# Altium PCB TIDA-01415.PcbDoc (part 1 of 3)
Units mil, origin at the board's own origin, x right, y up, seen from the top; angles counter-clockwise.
Board outline 3820.95 x 4648 mil, 4 copper layers (Top Layer, GND, PWR, Bottom Layer), stack 5.6 mil thick; 255 components, 113 nets, 599 pads, 415 vias.
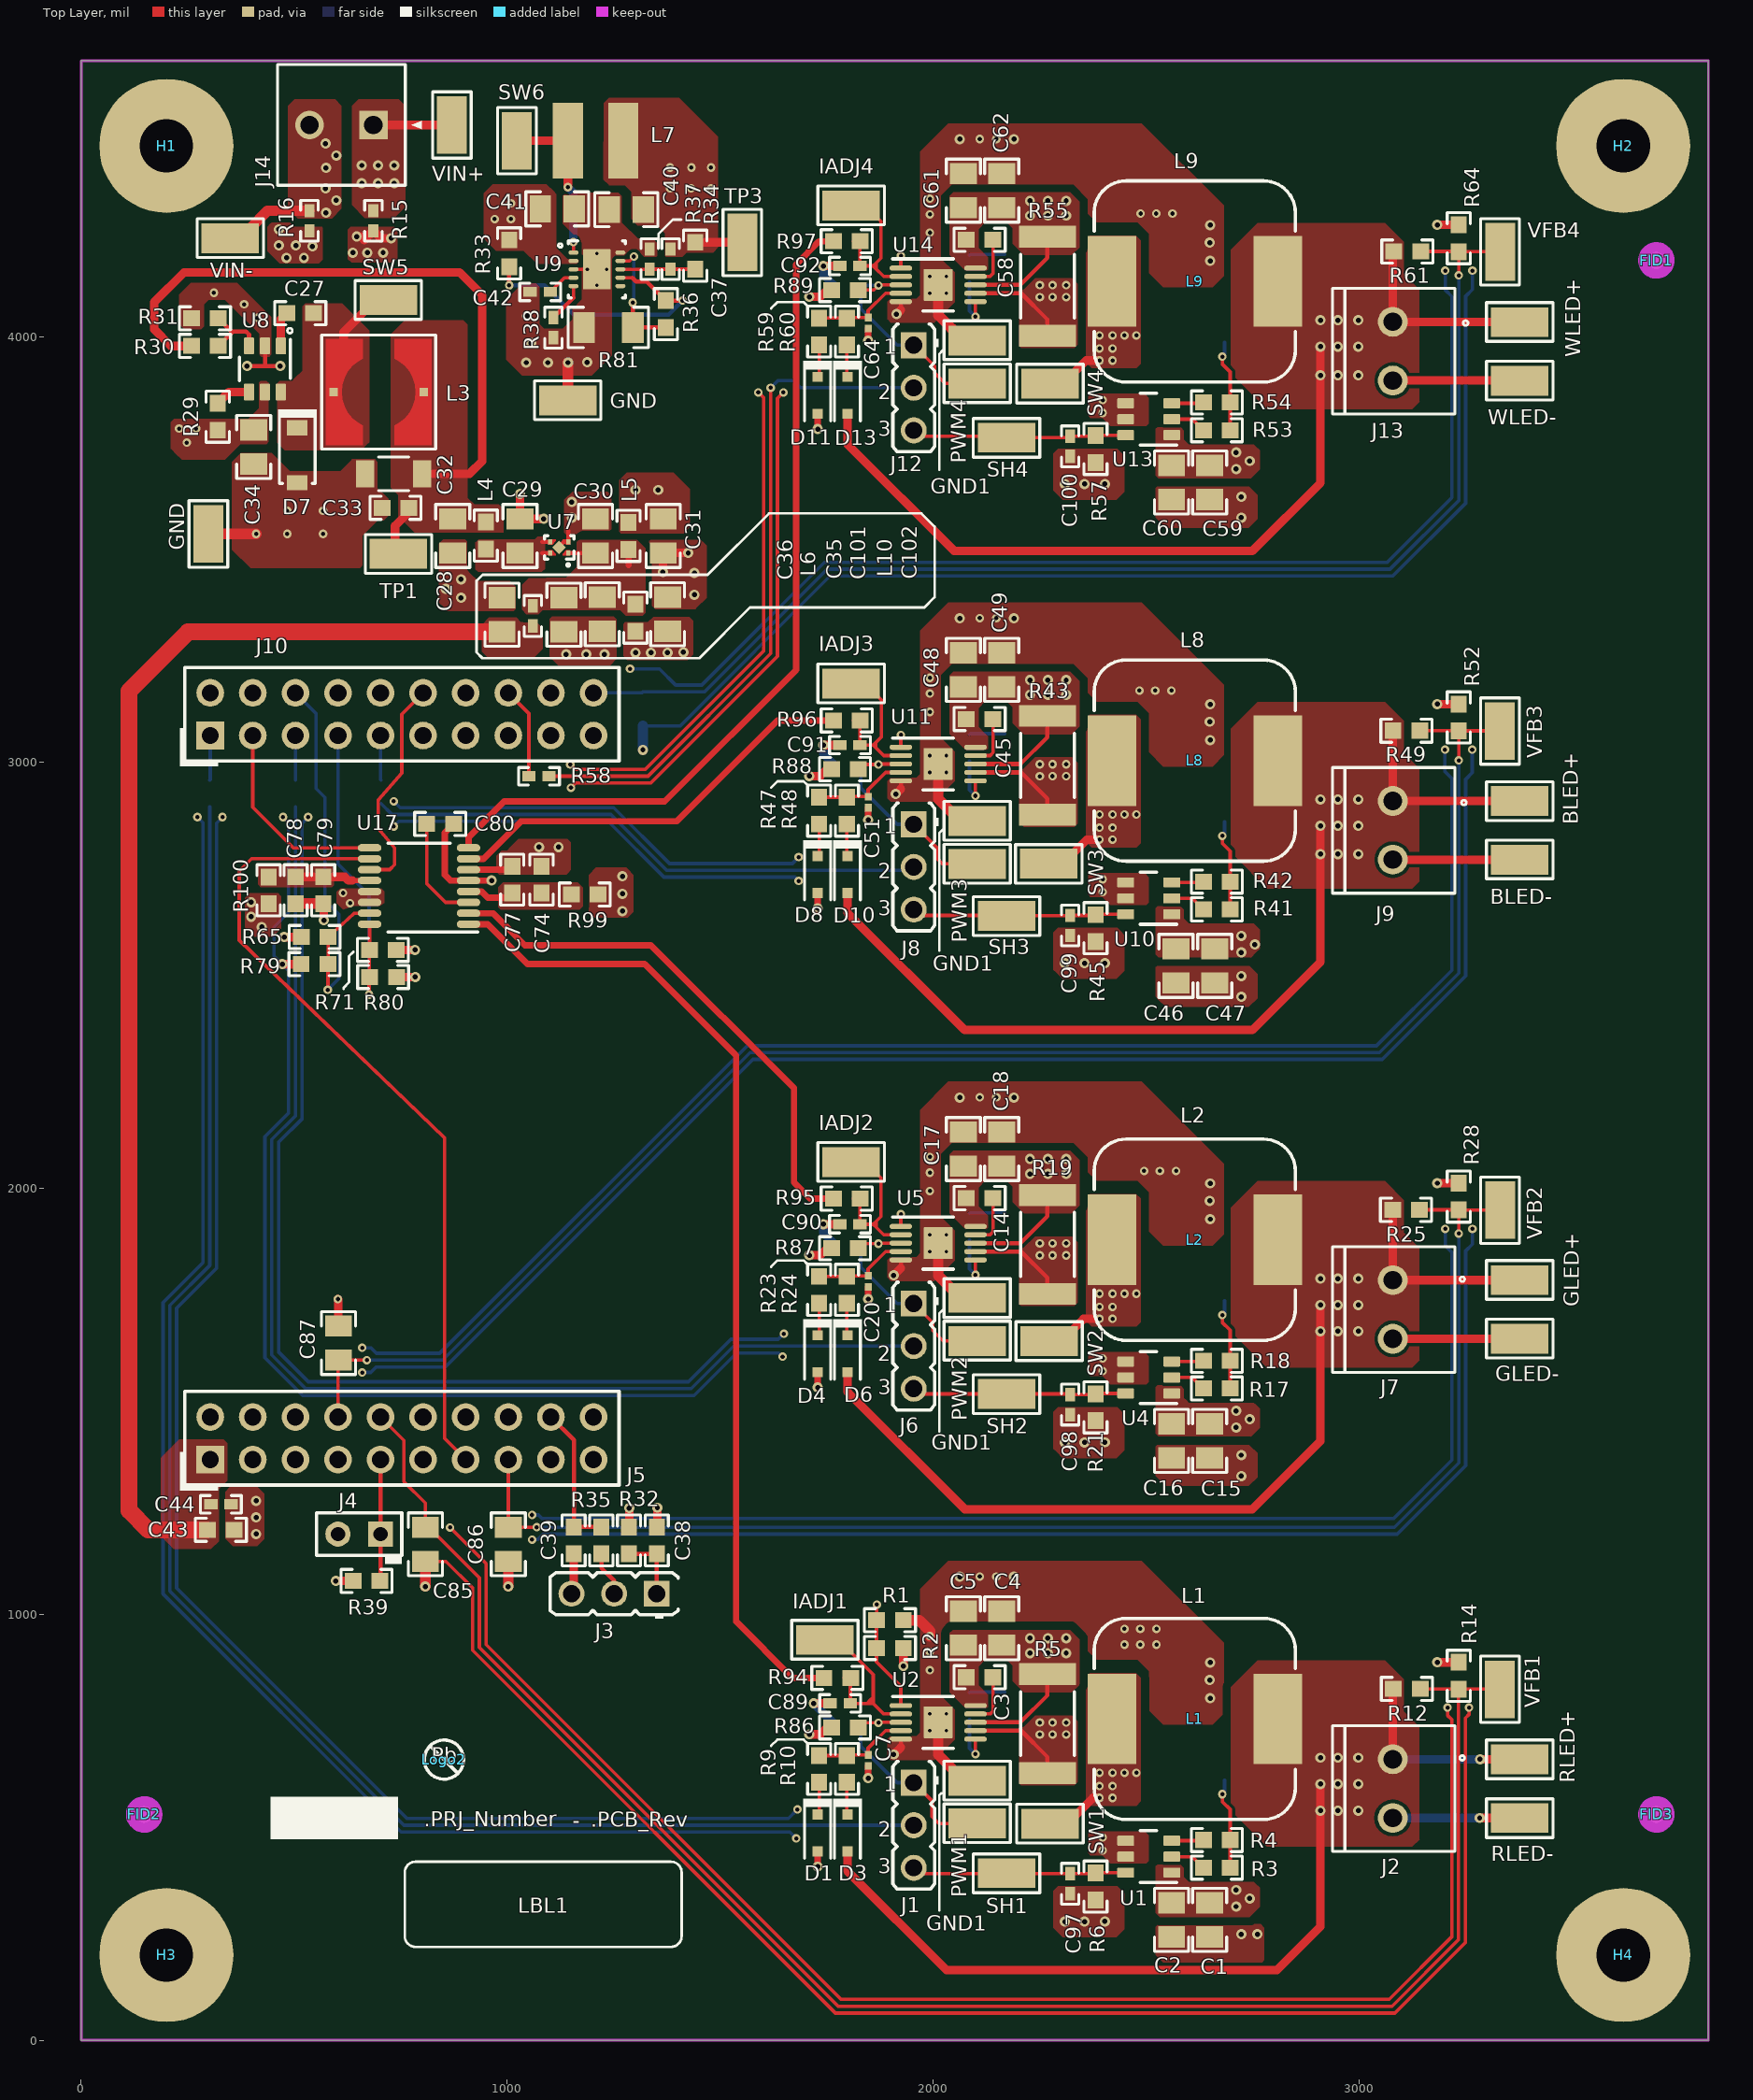
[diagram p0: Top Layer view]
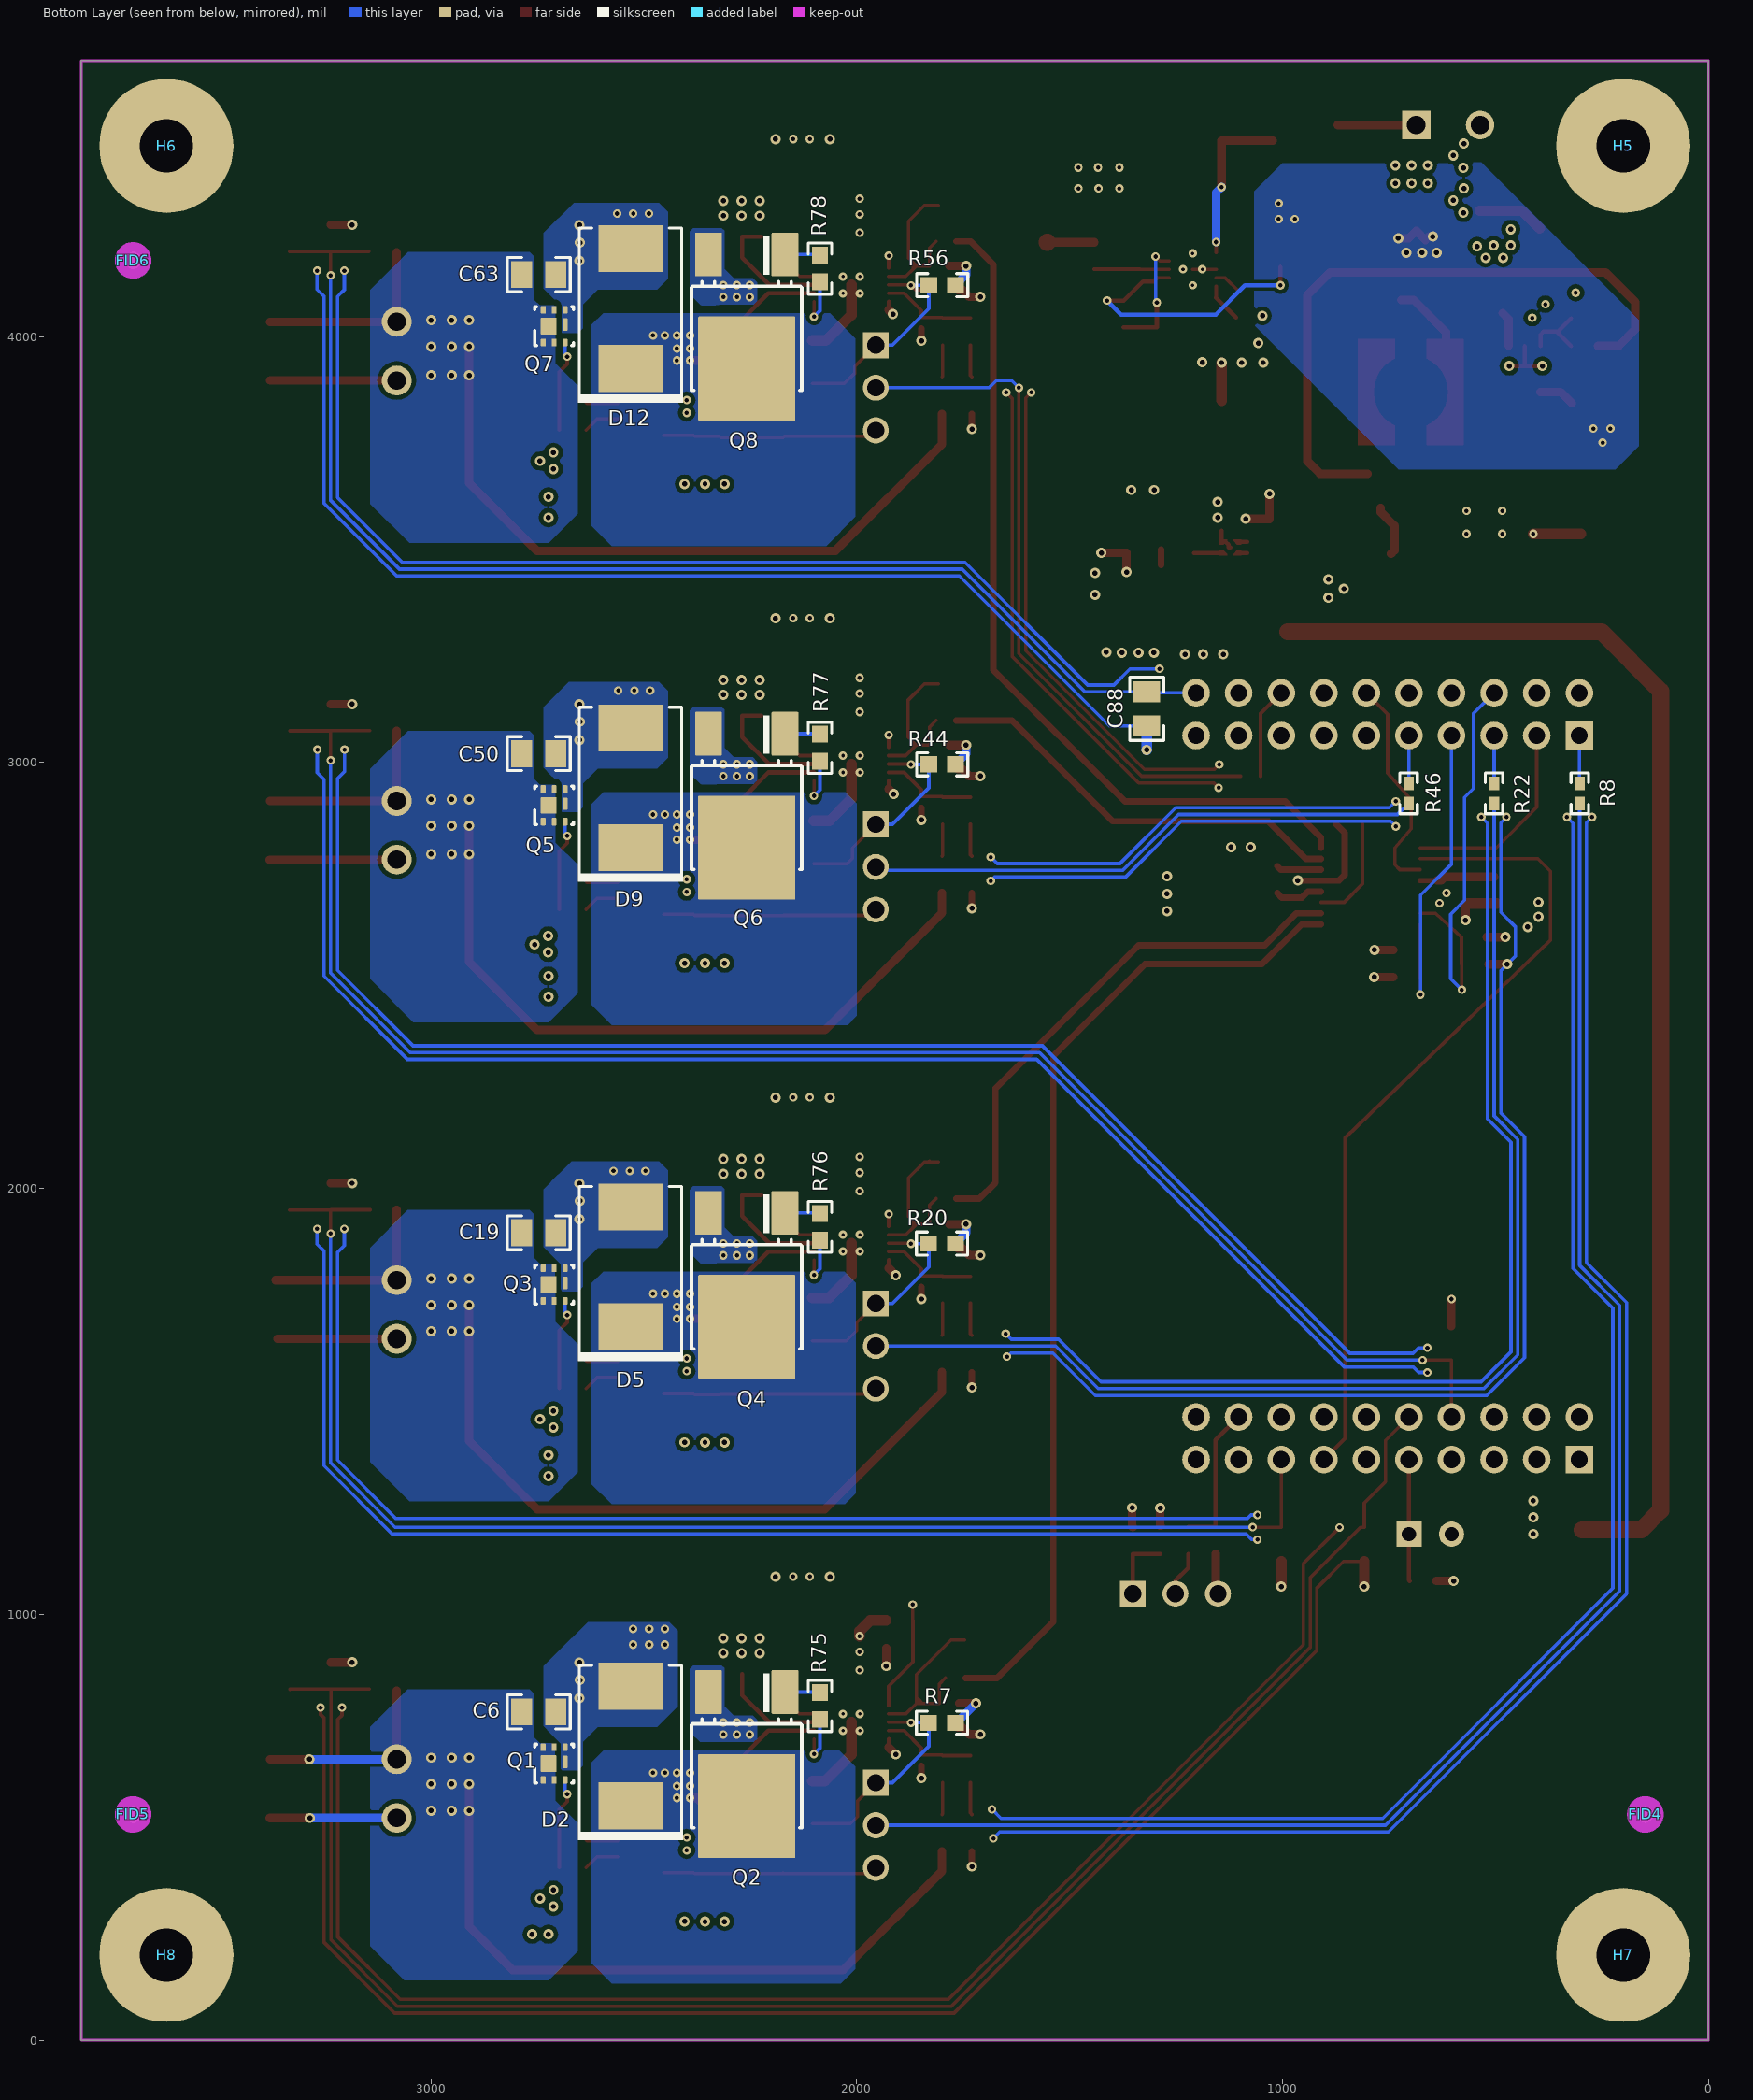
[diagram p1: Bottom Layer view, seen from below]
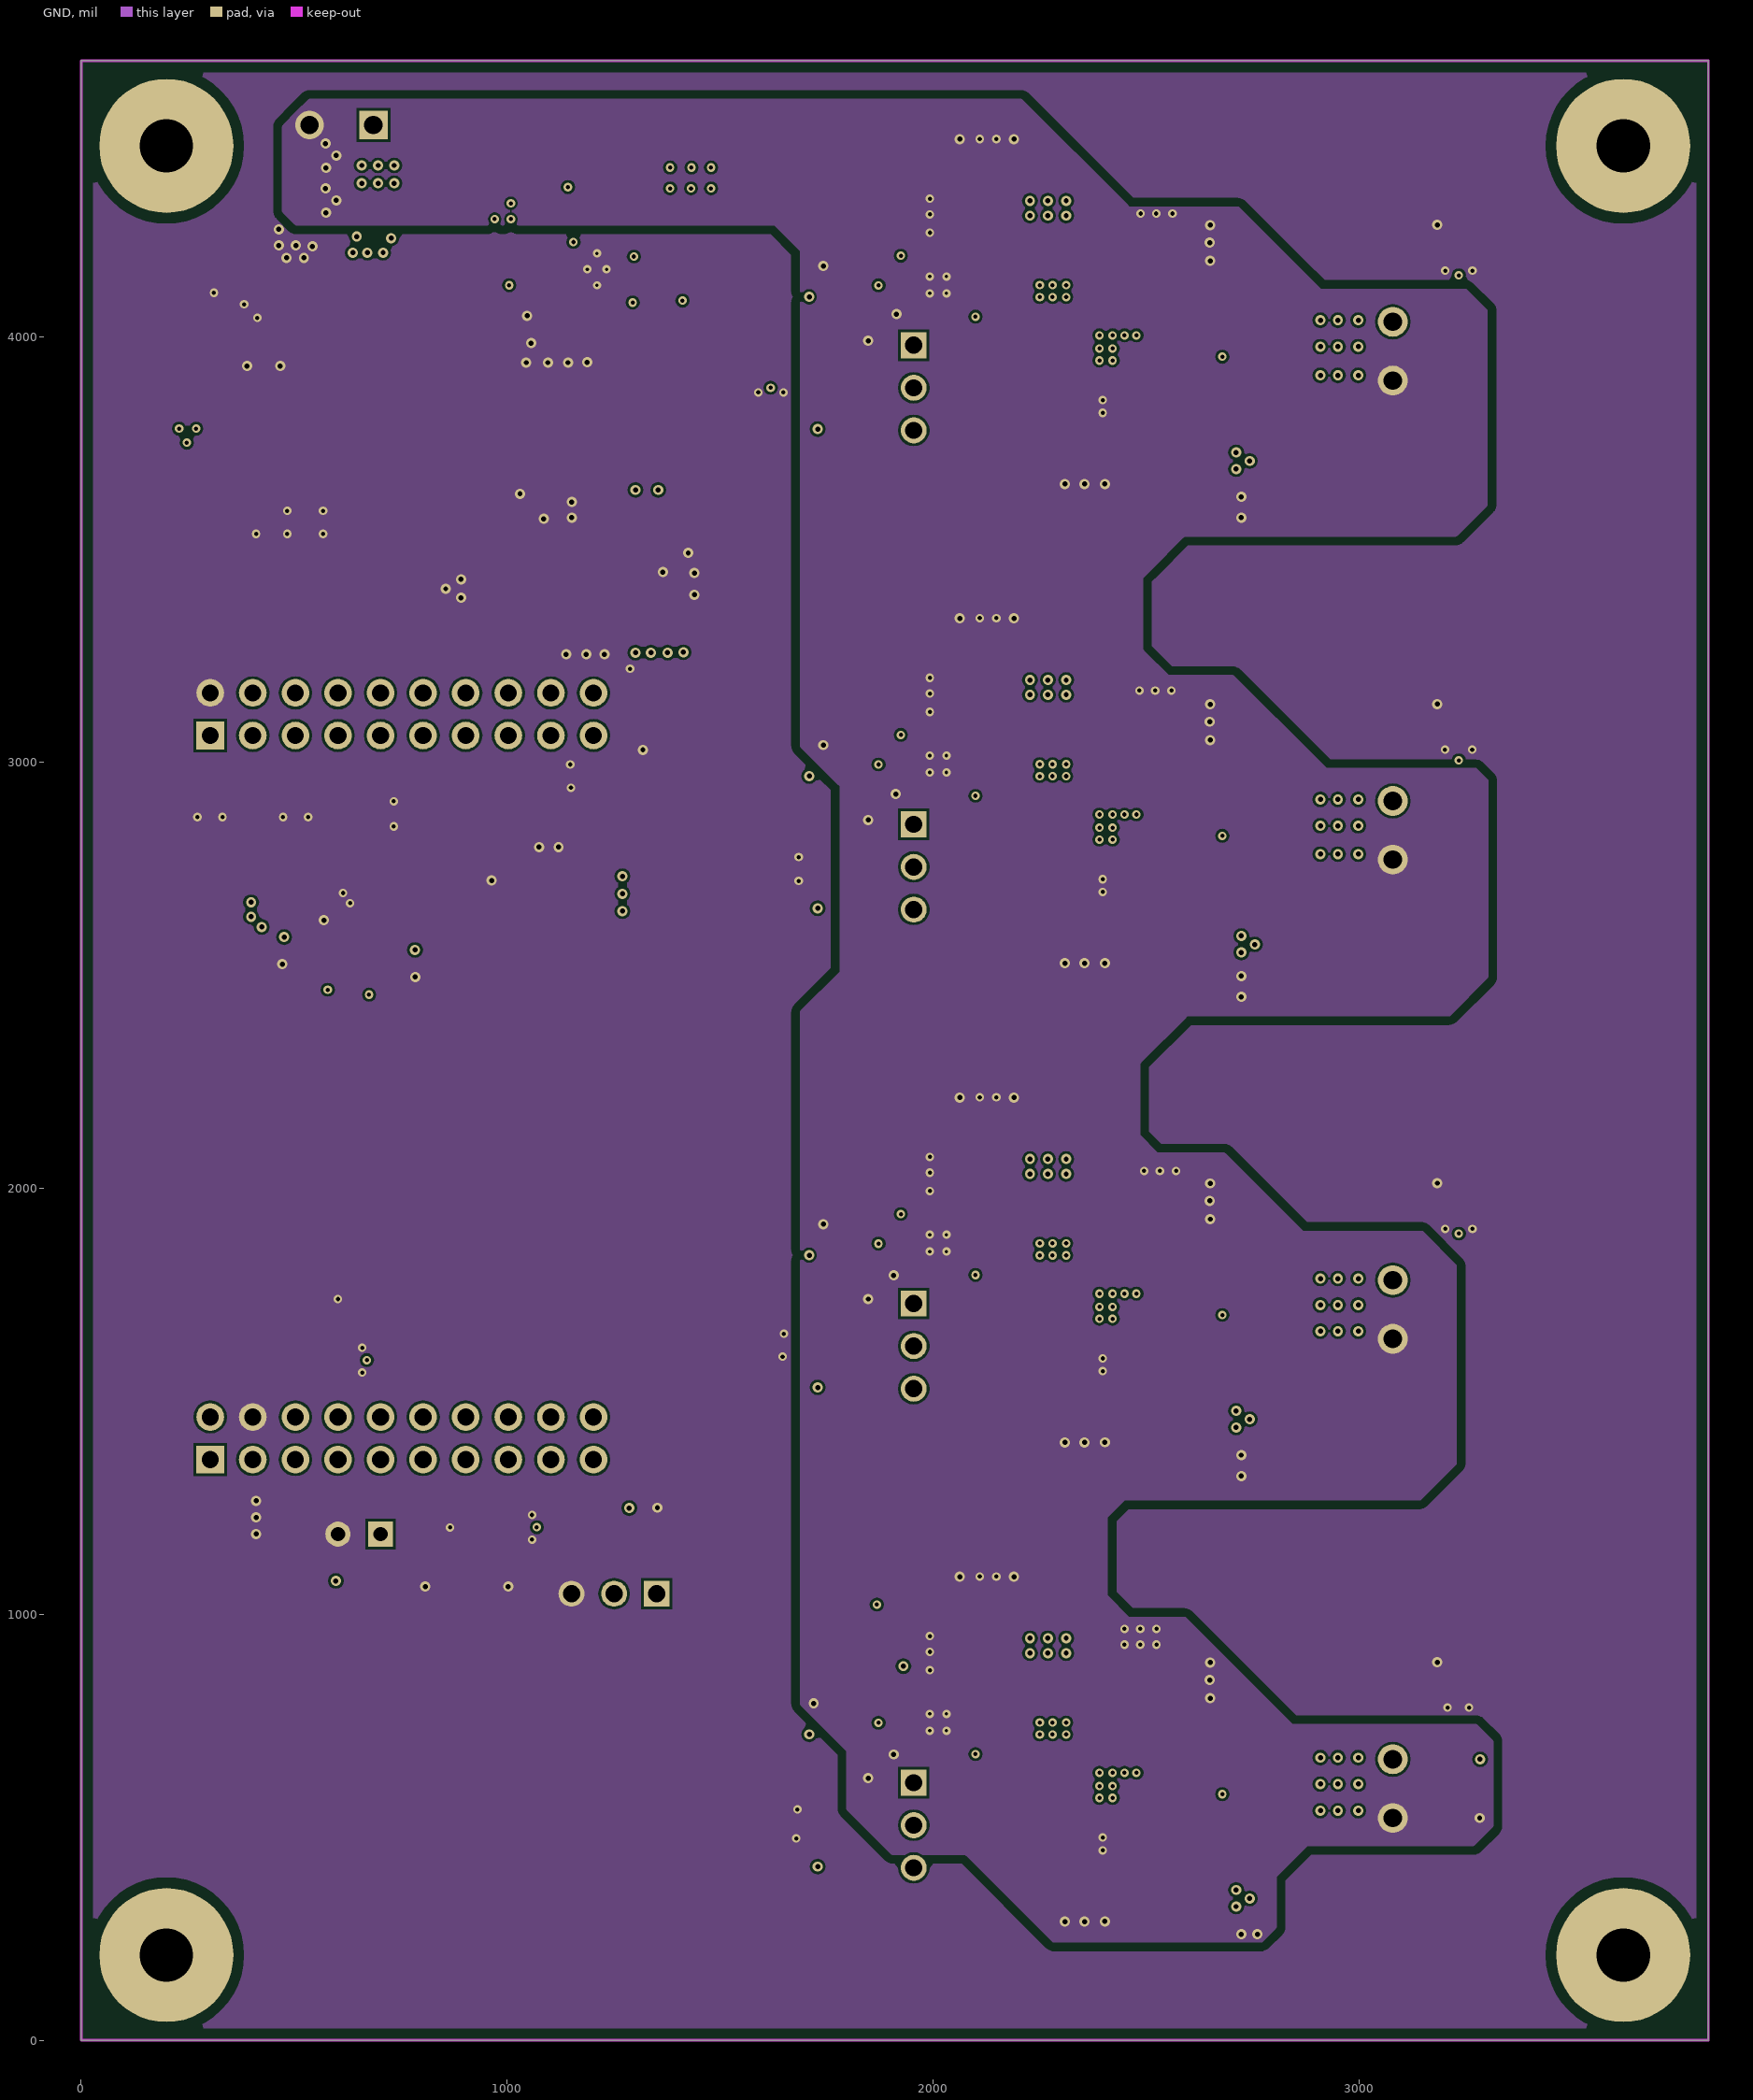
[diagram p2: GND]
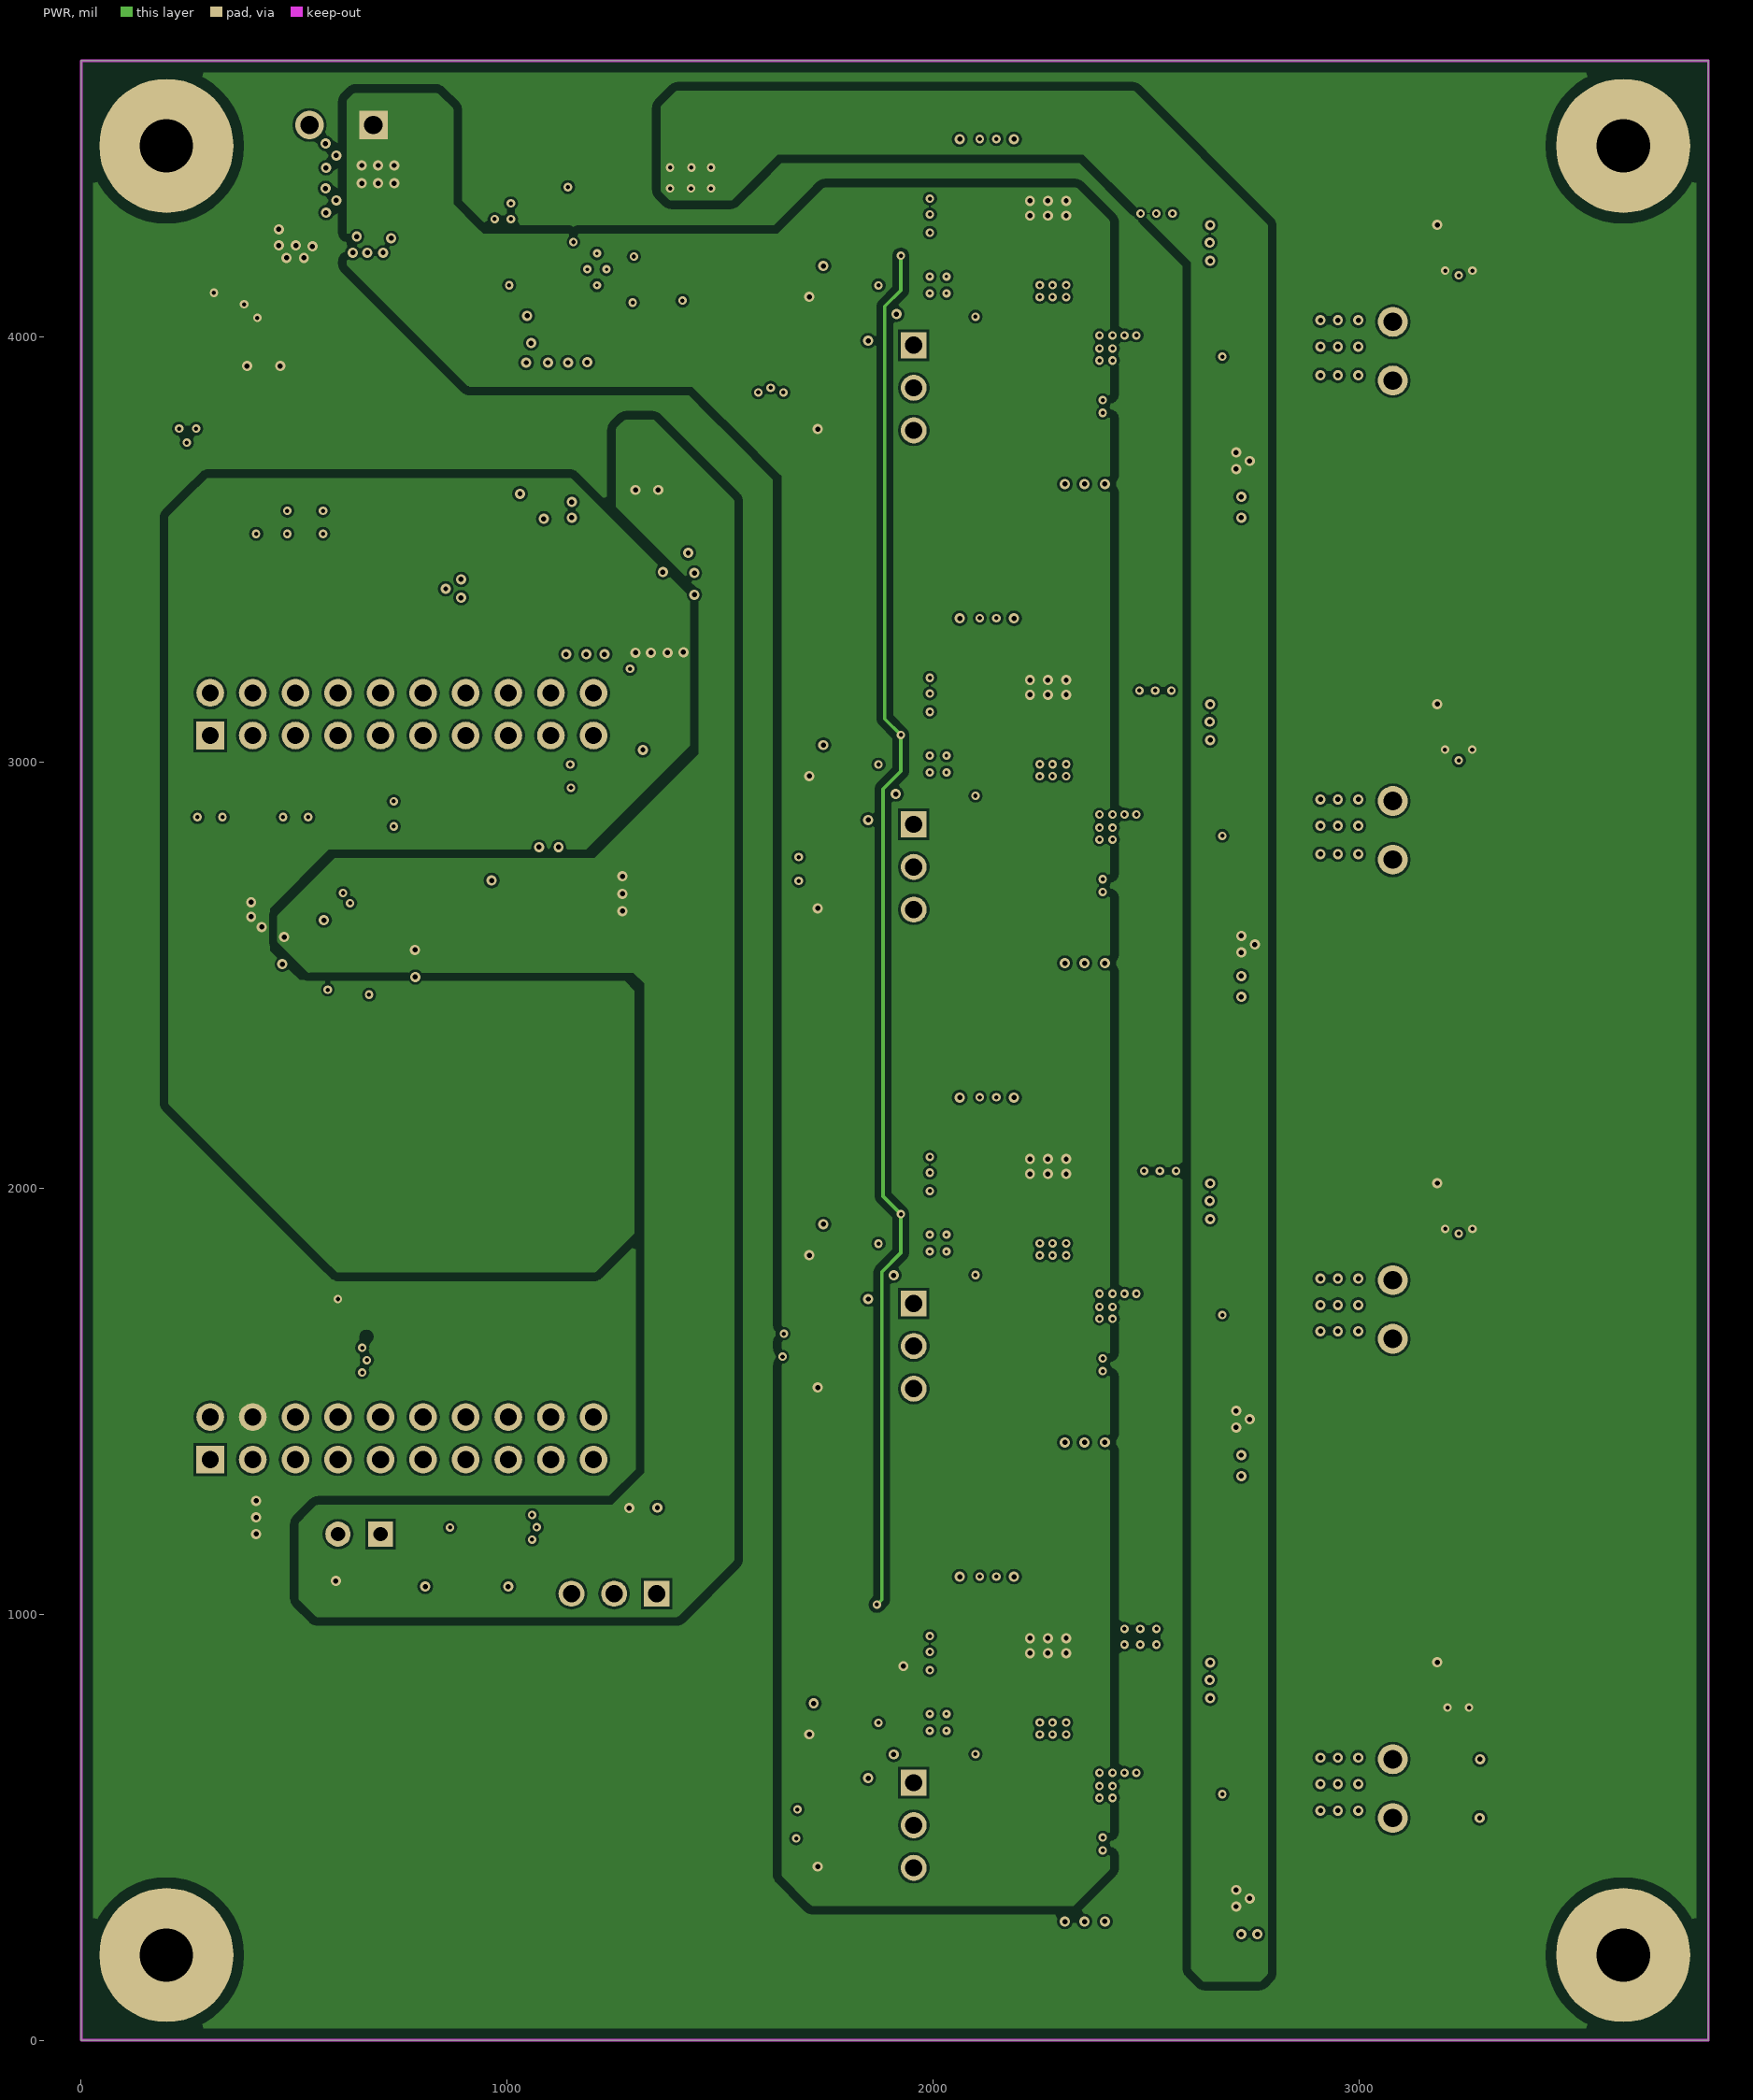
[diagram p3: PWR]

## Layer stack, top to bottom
Top Solder: solder mask 0.4, Solder Resist, Dk 3.5
Top Layer: signal copper 1.4
GND: signal copper 1.4
PWR: signal copper 1.4
Bottom Layer: signal copper 1.4
Bottom Solder: solder mask 0.4, Solder Resist, Dk 3.5

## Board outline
0,0 3820.95,0 3820.95,4648 0,4648

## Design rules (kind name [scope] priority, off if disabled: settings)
AcuteAngle [All] p1: minimum=4.50000000000000E+0001 checktracksonly=FALSE
AssemblyTestPointUsage [All] p1: valid=2
Clearance Clearance_5 [IsKeepOut vs InPolygon] p1: gap=25
Clearance Clearance_4 [OnTopLayer and InPolygon] p2: gap=8 except(7.87: SMDPad-SMDPad; 15: Poly-Poly)
Clearance MH [InComponentClass('MH') vs InPolygon] p3: gap=25 except(20: Poly-Poly)
Clearance Clearance_3 [OnLayer('PWR') and InPolygon] p4: gap=8 except(6: THPad-Poly Via-Poly; 7.87: SMDPad-SMDPad; 15: Track-Poly; 20: Poly-Poly)
Clearance Clearance_2 [OnLayer('GND') and inpolygon] p5: gap=8 except(6: THPad-Poly Via-Poly; 7.87: SMDPad-SMDPad; 20: Poly-Poly)
Clearance Clearance_1 [OnBottomLayer and InPolygon vs InPolygon] p6: gap=8 except(15: Poly-Poly)
Clearance Clearance_Poly [InPolygon] p7: gap=25 except(8: Track-Poly SMDPad-Poly; 10: Track-Track SMDPad-SMDPad THPad-Poly Via-Poly Fill-Poly; 20: Poly-Poly)
Clearance Clearance_Keepouts [((IsTrack Or IsArc) And Not InPoly) And IsFree and IsKeepOut vs ((IsTrack Or IsArc) And Not InPoly) And IsFree and IsKeepOut] p8: gap=0
Clearance [All] p9: gap=8 except(7.87: SMDPad-SMDPad; 20: Poly-Poly)
ComponentClearance ComponentClearance_MountingHoles_FiducialMarks [InComponentClass('Mounting Holes') vs InComponentClass('FiducialMark')] p1: gap=50 collisioncheckmode=3 verticalgap=10 showdistances=FALSE
ComponentClearance ComponentClearance_Shunt [InComponentClass('Header') vs InComponentClass('Shunt')] p2: gap=0 collisioncheckmode=3 verticalgap=0 showdistances=FALSE
ComponentClearance ComponentClearance_Logo [InComponentClass('Logo')] p3: gap=50 collisioncheckmode=3 verticalgap=10 showdistances=FALSE
ComponentClearance ComponentClearance_ScrewToNut [(HasFootprint('NY PMS 440 0025 PH')) vs (HasFootprint('Keystone_1902C'))] p4: gap=5 collisioncheckmode=3 verticalgap=10 showdistances=FALSE
ComponentClearance ComponentClearance_MountingHoles [InComponentClass('Mounting Holes')] p5: gap=250 collisioncheckmode=3 verticalgap=100000 showdistances=FALSE
ComponentClearance ComponentClearance_SmallPassives [HasFootprint('0201*') or HasFootprint('0402*') or HasFootprint('0508') or HasFootprint('0603*') or HasFootprint('0612') or HasFootprint('0805*') or HasFootprint('0815*') or HasFootprint('0830*') or HasFootprint('1206*') or HasFootprint('1210*') or HasFootprint('1808*') or HasFootprint('1812*') or HasFootprint('1825*') or HasFootprint('2010*') or HasFootprint('2220*') or HasFootprint('2225*') or HasFootprint('2512*') or HasFootprint('2728*') or HasFootprint('3518*') vs HasFootprint('0201*') or HasFootprint('0402*') or HasFootprint('0508') or HasFootprint('0603*') or HasFootprint('0612') or HasFootprint('0805*') or HasFootprint('0815*') or HasFootprint('0830*') or HasFootprint('1206*') or HasFootprint('1210*') or HasFootprint('1808*') or HasFootprint('1812*') or HasFootprint('1825*') or HasFootprint('2010*') or HasFootprint('2220*') or HasFootprint('2225*') or HasFootprint('2512*') or HasFootprint('2728*') or HasFootprint('3518*')] p6: gap=14.96 collisioncheckmode=3 verticalgap=10 showdistances=FALSE
ComponentClearance ComponentClearance_THtoSMT [IsThruComponent vs IsSMTComponent] p7: gap=40 collisioncheckmode=3 verticalgap=30 showdistances=FALSE
ComponentClearance ComponentClearance_THtoTH [IsThruComponent vs IsThruComponent] p8: gap=30 collisioncheckmode=3 verticalgap=30 showdistances=FALSE
ComponentClearance [All] p9: gap=30 collisioncheckmode=3 verticalgap=10 showdistances=FALSE
DiffPairsRouting [All] p1: maxlimit=100 minlimit=10 mostfreqgap=10 toplayer_minwidth=15 toplayer_maxwidth=15 toplayer_prefwidth=15 midlayer1_minwidth=15 midlayer1_maxwidth=15 midlayer1_prefwidth=15 midlayer2_minwidth=15 midlayer2_maxwidth=15 midlayer2_prefwidth=15 bottomlayer_minwidth=15 bottomlayer_maxwidth=15 bottomlayer_prefwidth=15 maxuncoupledlength=1000
FabricationTestPointUsage TestPointUsage [All] p1: valid=2 allowmultiple=FALSE
FabricationTestpoint Testpoint [All] p1: side=3 testpointundercomponent=TRUE minsize=40 maxsize=100 preferedsize=60 minholesize=0 maxholesize=40 preferedholesize=32 testpointgrid=1 allowsidetop=TRUE allowsidebottom=TRUE usegrid=TRUE gridtolerance=0.01
FanoutControl Fanout_LCC [IsLCC] p1: bgadir=Out bgaviamode=Centered fanoutstyle=Auto fanoutdirection=Alternating viagrid=1 // Fanout_LCC (Default Rule)
FanoutControl Fanout_BGA [IsBGA] p2: bgadir=Out bgaviamode=Centered fanoutstyle=Auto fanoutdirection=Alternating viagrid=1 // Fanout_BGA (Default Rule)
FanoutControl Fanout_Default [All] p4: bgadir=Out bgaviamode=Centered fanoutstyle=Auto fanoutdirection=Alternating viagrid=1 // Fanout_Default (Default Rule)
FanoutControl Fanout_Small [(CompPinCount < 5)] p5: bgadir=Out bgaviamode=Centered fanoutstyle=Auto fanoutdirection=OutThenIn viagrid=1 // Fanout_Small (Default Rule)
HoleSize [All] p1: absolutevalues=TRUE maxlimit=251 minlimit=7.87 maxpercent=80.000 minpercent=20.000
MinimumAnnularRing MinimumAnnularRing_ThermalPadVias [IsVia and InAnyComponent] p1: minimumring=5.91
MinimumAnnularRing [All] p2: minimumring=8
MinimumSolderMaskSliver MinimumSolderMaskSliver_Logo [InComponentClass('Logo') vs InComponentClass('Logo')] p1: minsoldermaskwidth=0.7
MinimumSolderMaskSliver [All] p2: minsoldermaskwidth=3.94
PlaneConnect [All] p1: planeconnectstyle=Relief reliefexpansion=10 reliefentries=4 reliefconductorwidth=10 reliefairgap=10
PolygonConnect [All] p1: connectstyle=Direct reliefconductorwidth=10 reliefentries=4 polygonreliefangle="90 Angle" airgapwidth=10
RoutingVias RoutingVias_1 [InNetClass('PWR')] p1: holewidth=12 width=24 viastyle="Through Hole" minholewidth=12 minwidth=24 maxholewidth=12 maxwidth=24
RoutingVias ThermalPadVias [IsVia and InAnyComponent] p2: holewidth=7.87 width=19.68 viastyle="Through Hole" minholewidth=7.87 minwidth=19.68 maxholewidth=12.99 maxwidth=23.62
RoutingVias [All] p3: holewidth=10 width=20 viastyle="Through Hole" minholewidth=10 minwidth=20 maxholewidth=10 maxwidth=20
SilkToBoardRegionClearance [Not ((IsComment or IsDesignator) And (Hide <> 'False')) and not InRegion(1000,500,4000,800)] p1:
SilkToSilkClearance SilkToSilkClearance_Pb-FreeLogo [(HasFootprint('Pb-Free_Overlay_Medium') OR HasFootprint('Pb-Free_Overlay_Small')) vs (HasFootprint('Pb-Free_Overlay_Medium') OR HasFootprint('Pb-Free_Overlay_Small'))] p1: silktosilkclearance=0
SilkToSilkClearance [All] p2: silktosilkclearance=4
SilkToSolderMaskClearance SilkToComponentPadClearance [IsPad and InAnycomponent] p1: minsilkscreentomaskgap=5 clearancetoexposedcopper=TRUE
SilkToSolderMaskClearance "Silk to Solder Mask Opening" [All] p2: minsilkscreentomaskgap=4 clearancetoexposedcopper=FALSE
SolderMaskExpansion [All] p1: expansion=1.97
Width PWR [InNetClass('PWR')] p1: maxlimit=100 minlimit=6 preferedwidth=15
Width [All] p2: maxlimit=100 minlimit=6 preferedwidth=8 checkconnectedcopper=TRUE
15 further rules are at their usual default settings.

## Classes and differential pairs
component class MH: H1 H2 H3 H4 H5 H6 H7 H8
component class Label: LBL1
component class AssemblyNote: ZZ1 ZZ2 ZZ3 ZZ4
component class FiducialMark: FID1 FID2 FID3 FID4 FID5 FID6
component class TIDA-01415_EVM_Hardware: FID1 FID2 FID3 FID4 FID5 FID6 H1 H2 H3 H4 H5 H6 H7 H8 LBL1 Logo2 ZZ1 ZZ2 ZZ3 ZZ4
component class "Mounting Holes": H1 H2 H3 H4
component class Header: J1 J3 J4 J5 J6 J8 J10 J12
component class TIDA-01415_BlankSheet: C1 C2 C3 C4 C5 C6 C7 C14 C15 C16 C17 C18 C19 C20 C89 C90 C97 C98 D1 D2 D3 D4 D5 D6 GLED+ GLED- GND GND1 IADJ1 IADJ2 J2 J7 L1 L2 PWM1 PWM2 Q1 Q2 Q3 Q4 R1 R2 R3 R4 R5 R6 R7 R9 R10 R17 R18 R19 R20 R21 R23 R24 R75 R76 R86 R87 R94 R95 RLED+ RLED- SH1 SH2 SW1 SW2 U1 U2 U4 U5
component class TIDA-01415_Page2: C27 C28 C29 C30 C31 C32 C33 C34 C35 C36 C37 C38 C39 C40 C41 C42 C85 C86 C87 C88 C101 C102 D7 GND J1 J3 J6 J8 J12 L3 L4 L5 L6 L7 L10 R12 R14 R25 R28 R29 R30 R31 R32 R33 R34 R35 R36 R37 R38 R49 R52 R61 R64 R81 SW5 SW6 TP1 TP3 U7 U8 U9
component class TIDA-01415_page4: C43 C44 C74 C77 C78 C79 C80 J4 J5 J10 R8 R22 R39 R46 R58 R65 R71 R79 R80 R99 R100 U17 VFB1 VFB2 VFB3 VFB4
component class TIDA-01415_page3: BLED+ BLED- C45 C46 C47 C48 C49 C50 C51 C58 C59 C60 C61 C62 C63 C64 C91 C92 C99 C100 D8 D9 D10 D11 D12 D13 GND GND1 IADJ3 IADJ4 J9 J13 J14 L8 L9 PWM3 PWM4 Q5 Q6 Q7 Q8 R15 R16 R41 R42 R43 R44 R45 R47 R48 R53 R54 R55 R56 R57 R59 R60 R77 R78 R88 R89 R96 R97 SH3 SH4 SW3 SW4 U10 U11 U13 U14 VIN+ VIN- WLED+ WLED-

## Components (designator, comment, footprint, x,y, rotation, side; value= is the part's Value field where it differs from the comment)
BLED+ "5015" Testpoint_Keystone_Miniature 3378,2910 r0 top
BLED- "5015" Testpoint_Keystone_Miniature 3378,2772 r180 top
C1 "C2012X7R1H104K085AA" 0805_HV 2649.75,282.54 r270 top
C2 "C2012X7R1H105K125AB" 0805_HV 2560.66,282.54 r270 top
C3 "C1608X7R1C105K080AC" 0603 2109.75,852.17 r0 top
C4 "C2012X7R1H225K125AC" 0805_HV 2161.54,967.65 r90 top
C5 "C2012X7R1H225K125AC" 0805_HV 2071.6,967.65 r90 top
C6 "885012207092" 0805_HV 2746.43,770.9 r180 bottom
C7 "CGA1A2X7R1H471K030BA" 0201_033 1847.95,657 r270 top
C14 "C1608X7R1C105K080AC" 0603 2109.75,1977.17 r0 top
C15 "C2012X7R1H104K085AA" 0805_HV 2649.75,1407.54 r270 top
C16 "C2012X7R1H105K125AB" 0805_HV 2560.66,1407.54 r270 top
C17 "C2012X7R1H225K125AC" 0805_HV 2071.6,2092.65 r90 top
C18 "C2012X7R1H225K125AC" 0805_HV 2161.54,2092.65 r90 top
C19 "885012207092" 0805_HV 2746.43,1895.9 r180 bottom
C20 "CGA1A2X7R1H471K030BA" 0201_033 1847.95,1782 r270 top
C27 "C0603C334K4RACTU" 0603 514.5,4055 r180 top
C28 "C2012X7R1C225K125AB" 0805_HV 872.5,3532 r270 top
C29 "C2012X7R1C225K125AB" 0805_HV 1030.48,3532.09 r90 top
C30 "C2012X7R1C225K125AB" 0805_HV 1207.5,3532.09 r90 top
C31 "C2012X7R1C225K125AB" 0805_HV 1366.5,3532.09 r270 top
C32 "GRM31CR61C226KE15L" 1206_180 733.5,3678 r180 top
C33 "GRT188C81A106ME13D" 0603 738,3598 r180 top
C34 "C2012X7R1H225K125AC" 0805_HV 405,3740.85 r270 top
C35 "C2012X7R1C225K125AB" 0805_HV 1133.5,3347 r270 top
C36 "C2012X7R1C225K125AB" 0805_HV 988.13,3347 r90 top
C37 "GCM188R71E473KA37D" 0603 1442,4190 r270 top
C38 "GRT188C81A106ME13D" 0603 1351.46,1173.5 r90 top
C39 "GRM188R71E104KA01D" 0603 1156.46,1173.5 r270 top
C40 "CGA4J1X7S1C106K125AC" 0805_HV 1280,4298 r180 top
C41 "C2012X7R1H225K125AC" 0805_HV 1118,4300 r0 top
C42 "GRM155R71C563KA88D" 0402 1078,4105 r180 top
C43 "GRT188C81A106ME13D" 0603 327.99,1198.49 r0 top
C44 "GRM155R61A104KA01D" 0402 327.99,1258.49 r180 top
C45 "C1608X7R1C105K080AC" 0603 2109.75,3102.17 r0 top
C46 "C2012X7R1H104K085AA" 0805_HV 2571,2522.53 r270 top
C47 "C2012X7R1H105K125AB" 0805_HV 2662,2522.53 r270 top
C48 "C2012X7R1H225K125AC" 0805_HV 2071.6,3217.65 r90 top
C49 "C2012X7R1H225K125AC" 0805_HV 2161.54,3217.65 r90 top
C50 "885012207092" 0805_HV 2746.43,3020.9 r180 bottom
C51 "CGA1A2X7R1H471K030BA" 0201_033 1847.95,2907 r270 top
C58 "C1608X7R1C105K080AC" 0603 2109.75,4227.17 r0 top
C59 "C2012X7R1H104K085AA" 0805_HV 2649.75,3657.54 r270 top
C60 "C2012X7R1H105K125AB" 0805_HV 2560.66,3657.54 r270 top
C61 "C2012X7R1H225K125AC" 0805_HV 2071.6,4342.65 r90 top
C62 "C2012X7R1H225K125AC" 0805_HV 2161.54,4342.65 r90 top
C63 "885012207092" 0805_HV 2746.43,4145.9 r180 bottom
C64 "CGA1A2X7R1H471K030BA" 0201_033 1847.95,4032 r270 top
C74 "C1608X7R1C105K080AC" 0603 1081,2725 r90 top
C77 "GRM188R71H104KA93D" 0603 1012.31,2725.15 r270 top
C78 "GRT188C81A106ME13D" 0603 503.31,2700.15 r270 top
C79 "GRM188R71H104KA93D" 0603 568.31,2700.15 r90 top
C80 "C1608X7R1E154K080AA" 0603 843,2856 r180 top
C85 "C2012X7R1H104K085AA" 0805_HV 808,1164.5 r90 top
C86 "C2012X7R1H104K085AA" 0805_HV 1003,1164.5 r90 top
C87 "C2012X7R1H104K085AA" 0805_HV 604,1637 r270 top
C88 "C2012X7R1H104K085AA" 0805_HV 1319,3126 r90 bottom
C89 "C1005X7R1E104M050BB" 0402 1782.38,791 r0 top
C90 "C1005X7R1E104M050BB" 0402 1805.38,1916 r0 top
C91 "C1005X7R1E104M050BB" 0402 1805.38,3041 r0 top
C92 "C1005X7R1E104M050BB" 0402 1805.38,4166 r0 top
C97 "885012005056" 0402 2322.48,367.45 r270 top
C98 "885012005056" 0402 2322.48,1492.45 r270 top
C99 "885012005056" 0402 2322.48,2617.45 r270 top
C100 "885012005056" 0402 2322.48,3742.45 r270 top
C101 "C2012X7R1C225K125AB" 0805_HV 1223.5,3348 r270 top
C102 "C2012X7R1C225K125AB" 0805_HV 1377,3348 r90 top
D1 "ZLLS410TA" SOD-323 1729.43,487 r270 top
D2 "CDBC560-G" SMC 2531,690.9 r90 bottom
D3 "ZLLS410TA" SOD-323 1799.43,487 r270 top
D4 "ZLLS410TA" SOD-323 1729.43,1612 r270 top
D5 "CDBC560-G" SMC 2531,1815.9 r90 bottom
D6 "ZLLS410TA" SOD-323 1799.43,1612 r270 top
D7 "MBR1H100SFT3G" SOD-123FL 507.5,3721.53 r270 top
D8 "ZLLS410TA" SOD-323 1729.43,2737 r270 top
D9 "CDBC560-G" SMC 2531,2940.9 r90 bottom
D10 "ZLLS410TA" SOD-323 1799.43,2737 r270 top
D11 "ZLLS410TA" SOD-323 1729.43,3862 r270 top
D12 "CDBC560-G" SMC 2531,4065.9 r90 bottom
D13 "ZLLS410TA" SOD-323 1799.43,3862 r270 top
FID1 "Fiducial" Fiducial10-20 3699,4179 r0 top
FID2 "Fiducial" Fiducial10-20 148,530.31 r0 top
FID3 "Fiducial" Fiducial10-20 3699,530.31 r0 top
FID4 "Fiducial" Fiducial10-20 148,530.31 r90 bottom
FID5 "Fiducial" Fiducial10-20 3699,530.31 r90 bottom
FID6 "Fiducial" Fiducial10-20 3699,4179 r90 bottom
GLED+ "5015" Testpoint_Keystone_Miniature 3378,1784.79 r180 top
GLED- "5015" Testpoint_Keystone_Miniature 3378,1647 r180 top
GND "5015" Testpoint_Keystone_Miniature 1142.53,3850 r180 top
GND "5015" Testpoint_Keystone_Miniature 299,3536.71 r270 top
GND1 "5015" Testpoint_Keystone_Miniature 2104,2863 r180 top
GND1 "5015" Testpoint_Keystone_Miniature 2104,3991 r180 top
GND1 "5015" Testpoint_Keystone_Miniature 2104,609 r180 top
GND1 "5015" Testpoint_Keystone_Miniature 2104,1743 r0 top
H1 "NY PMS 440 0025 PH" "NY PMS 440 0025 PH" 200,4448 r0 top locked
H2 "NY PMS 440 0025 PH" "NY PMS 440 0025 PH" 3620.95,4448 r0 top
H3 "NY PMS 440 0025 PH" "NY PMS 440 0025 PH" 200,200 r0 top locked
H4 "NY PMS 440 0025 PH" "NY PMS 440 0025 PH" 3620.95,200 r0 top
H5 "1902C" Keystone_1902C 200,4448 r180 bottom
H6 "1902C" Keystone_1902C 3620.95,4448 r180 bottom
H7 "1902C" Keystone_1902C 200,200 r180 bottom locked
H8 "1902C" Keystone_1902C 3620.95,200 r180 bottom locked
IADJ1 "5015" Testpoint_Keystone_Miniature 1746.31,940 r180 top
IADJ2 "5015" Testpoint_Keystone_Miniature 1808,2062 r180 top
IADJ3 "5015" Testpoint_Keystone_Miniature 1808,3185 r180 top
IADJ4 "5015" Testpoint_Keystone_Miniature 1808,4307.95 r180 top
J1 "0022284033" Molex_0022284033 1955,504.9 r270 top
J2 "1751248" CONN_1751248 3080,590.9 r270 top
J3 "0022284033" Molex_0022284033 1251.46,1048.5 r180 top
J4 "800-10-002-10-001000" Mill-Max_800-10-002-10-001000 652.99,1188.49 r180 top
J5 "PEC10DAAN" SULLINS_PEC10DAAN 752.99,1413.49 r90 top locked
J6 "0022284033" Molex_0022284033 1955,1629.9 r270 top
J7 "1751248" CONN_1751248 3080,1715.9 r270 top
J8 "0022284033" Molex_0022284033 1955,2754.9 r270 top
J9 "1751248" CONN_1751248 3080,2840.9 r270 top
J10 "PEC10DAAN" SULLINS_PEC10DAAN 752.99,3113.49 r90 top locked
J12 "0022284033" Molex_0022284033 1955,3879.9 r270 top
J13 "1751248" CONN_1751248 3080,3965.9 r270 top
J14 "1727010" PhoenixConact_1727010 611,4497 r180 top
L1 "744770147" "WE-PD_1245_METAL BASE" 2615,754.53 r90 top locked
L2 "744770147" "WE-PD_1245_METAL BASE" 2615,1879.53 r90 top locked
L3 "744053150" WE-TPC-LH 698.5,3869.87 r0 top
L4 "742792662" 0603 950,3533 r270 top
L5 "742792662" 0603 1285.5,3532 r90 top
L6 "BLM15AG221SN1D" 0402 1060.5,3344 r270 top
L7 "SDR0403-331KL" SDR0403 1208,4460 r0 top
L8 "744770147" "WE-PD_1245_METAL BASE" 2615,3004.53 r90 top locked
L9 "744770147" "WE-PD_1245_METAL BASE" 2615,4129.53 r90 top locked
L10 "742792662" 0603 1301.5,3340 r270 top
LBL1 "Size: 0.65\" x 0.20 \"" Label_650x200 1084.99,319.35 r0 top
Logo2 "Pb-Free Symbol" Pb-Free_Overlay_Small 852,659 r0 top
PWM1 "5015" Testpoint_Keystone_Miniature 2104,509 r180 top
PWM2 "5015" Testpoint_Keystone_Miniature 2104,1642 r180 top
PWM3 "5015" Testpoint_Keystone_Miniature 2104,2762 r180 top
PWM4 "5015" Testpoint_Keystone_Miniature 2104,3890 r180 top
Q1 "CSD19538Q2" DQK0006C 2710.41,649.51 r90 bottom
Q2 "ZXMP10A16KTC" DPAK 2258,683.9 r270 bottom locked
Q3 "CSD19538Q2" DQK0006C 2710.41,1774.51 r90 bottom
Q4 "ZXMP10A16KTC" DPAK 2258,1808.9 r270 bottom locked
Q5 "CSD19538Q2" DQK0006C 2710.41,2899.51 r90 bottom
Q6 "ZXMP10A16KTC" DPAK 2258,2933.9 r270 bottom locked
Q7 "CSD19538Q2" DQK0006C 2710.41,4024.51 r90 bottom
Q8 "ZXMP10A16KTC" DPAK 2258,4058.9 r270 bottom locked
R1 "CRCW06035K62FKEA" 0603 1899.15,986.12 r180 top
R2 "CRCW060349K9FKEA" 0603 1899.15,921.12 r180 top
R3 "CRCW06031R00JNEA" 0603 2666.72,405.37 r180 top
R4 "CRCW06031R00JNEA" 0603 2666.72,470.37 r180 top
R5 "CSRN2512FKR300" 2512 2269,743.53 r90 top locked
R6 "CRCW060310K0FKEA" 0603 2381.93,361.17 r90 top
R7 "CRCW060310K0FKEA" 0603 1799.55,745.45 r0 bottom
R8 "CRCW0402470RJNED" 0402 302,2927.5 r270 bottom
R9 "CRCW06033M16FKEA" 0603 1732.95,637 r90 top
R10 "CRCW06034K53FKEA" 0603 1797.95,637 r270 top
R12 "CRCW0603110KFKEA" 0603 3113,825 r180 top
R14 "CRCW060314K0FKEA" 0603 3235,855.9 r270 top
R15 "CRCW04020000Z0ED" 0402 686,4272 r270 top
R16 "CRCW04020000Z0ED" 0402 536,4272 r270 top
R17 "CRCW06031R00JNEA" 0603 2666.72,1530.37 r180 top
R18 "CRCW06031R00JNEA" 0603 2666.72,1595.37 r180 top
R19 "CSRN2512FKR300" 2512 2269,1868.53 r90 top
R20 "CRCW060310K0FKEA" 0603 1799.55,1870.45 r0 bottom
R21 "CRCW060310K0FKEA" 0603 2381.93,1486.17 r90 top
R22 "CRCW0402470RJNED" 0402 503,2927.5 r270 bottom
R23 "CRCW06033M16FKEA" 0603 1732.95,1762 r90 top
R24 "CRCW06034K53FKEA" 0603 1797.95,1762 r270 top
R25 "CRCW0603110KFKEA" 0603 3111,1950 r180 top
R28 "CRCW060314K0FKEA" 0603 3235,1980.9 r270 top
R29 "CRCW0603100KFKEA" 0603 320.5,3812 r270 top
R30 "CRCW0603110KFKEA" 0603 290.61,3978.02 r180 top
R31 "RC0603FR-0730KL" 0603 290.61,4043.02 r0 top
R32 "RC0603FR-07100RL" 0603 1286.46,1173.5 r90 top
R33 "CRCW0603110KFKEA" 0603 1005,4195.46 r90 top
R34 "CRCW0402887KFKED" 0402 1384,4182 r90 top
R35 "RC0603FR-071K5L" 0603 1221.46,1173.5 r270 top
R36 "CRCW060312K4FKEA" 0603 1373,4053 r90 top
R37 "CRCW0402124KFKED" 0402 1335,4182 r270 top
R38 "CRCW0402182KFKED" 0402 1109,4021 r90 top
R39 "CRCW0603100KFKEA" 0603 670,1078.5 r180 top
R41 "CRCW06031R00JNEA" 0603 2666.72,2655.37 r180 top
R42 "CRCW06031R00JNEA" 0603 2666.72,2720.37 r180 top
R43 "CSRN2512FKR300" 2512 2269,2993.53 r90 top
R44 "CRCW060310K0FKEA" 0603 1799,2996 r0 bottom
R45 "CRCW060310K0FKEA" 0603 2381.93,2611.17 r90 top
R46 "CRCW0402470RJNED" 0402 704,2927.5 r270 bottom
R47 "CRCW06033M16FKEA" 0603 1732.95,2887 r90 top
R48 "CRCW06034K53FKEA" 0603 1797.95,2887 r270 top
R49 "CRCW0603110KFKEA" 0603 3112,3075 r180 top
R52 "CRCW060314K0FKEA" 0603 3235,3105.9 r270 top
R53 "CRCW06031R00JNEA" 0603 2666.72,3780.37 r180 top
R54 "CRCW06031R00JNEA" 0603 2666.72,3845.37 r180 top
R55 "CSRN2512FKR300" 2512 2269,4118.53 r90 top
R56 "CRCW060310K0FKEA" 0603 1799,4121 r0 bottom
R57 "CRCW060310K0FKEA" 0603 2381.93,3736.17 r90 top
R58 "CRCW0402470RJNED" 0402 1075,2968 r0 top
R59 "CRCW06033M16FKEA" 0603 1732.95,4012 r90 top
R60 "CRCW06034K53FKEA" 0603 1797.95,4012 r270 top
R61 "CRCW0603110KFKEA" 0603 3114,4200 r180 top
R64 "CRCW060314K0FKEA" 0603 3235,4230.9 r270 top
R65 "CRCW0603100KFKEA" 0603 548.31,2590.15 r180 top
R71 "CRCW0603100KFKEA" 0603 708.31,2560.15 r0 top
R75 "CRCW06030000Z0EA" 0603 2086,784.9 r90 bottom
R76 "CRCW06030000Z0EA" 0603 2086,1909.9 r90 bottom
R77 "CRCW06030000Z0EA" 0603 2086,3034.9 r90 bottom
R78 "CRCW06030000Z0EA" 0603 2086,4159.9 r90 bottom
R79 "CRCW06030000Z0EA" 0603 548,2526.5 r0 top
R80 "CRCW06030000Z0EA" 0603 709,2496.5 r180 top
R81 "CRCW1206412RFKEA" 1206 1238,4021.5 r0 top
R86 "CRCW0603100KFKEA" 0603 1793.43,734.48 r180 top
R87 "CRCW0603100KFKEA" 0603 1793.43,1859.48 r180 top
R88 "CRCW0603100KFKEA" 0603 1793.43,2984.48 r180 top
R89 "CRCW0603100KFKEA" 0603 1793.43,4109.48 r180 top
R94 "RC0603FR-07100RL" 0603 1775.67,850.83 r180 top
R95 "RC0603FR-07100RL" 0603 1797.67,1976.33 r180 top
R96 "RC0603FR-07100RL" 0603 1797.67,3098.83 r180 top
R97 "RC0603FR-07100RL" 0603 1797.67,4223.83 r180 top
R99 "CRCW060310R0FKEA" 0603 1182.35,2690 r180 top
R100 "CRCW060310R0FKEA" 0603 440.11,2700 r90 top
RLED+ "5015" Testpoint_Keystone_Miniature 3378,660 r0 top
RLED- "5015" Testpoint_Keystone_Miniature 3378,522 r0 top
SH1 "5015" Testpoint_Keystone_Miniature 2172.88,392.45 r0 top
SH2 "5015" Testpoint_Keystone_Miniature 2172.88,1517.66 r0 top
SH3 "5015" Testpoint_Keystone_Miniature 2172.88,2640.17 r0 top
SH4 "5015" Testpoint_Keystone_Miniature 2172.88,3763 r0 top
SW1 "5015" Testpoint_Keystone_Miniature 2275,508 r180 top
SW2 "5015" Testpoint_Keystone_Miniature 2273,1642 r0 top
SW3 "5015" Testpoint_Keystone_Miniature 2272,2762.5 r0 top
SW4 "5015" Testpoint_Keystone_Miniature 2275,3890 r0 top
SW5 "5015" Testpoint_Keystone_Miniature 721.11,4086.42 r0 top
SW6 "5015" Testpoint_Keystone_Miniature 1022.94,4459.96 r90 top
TP1 "5015" Testpoint_Keystone_Miniature 745,3490.07 r0 top
TP3 "5015" Testpoint_Keystone_Miniature 1553,4221 r270 top
U1 "UCC27511DBVR" DBV0006A_N 2506.93,431.17 r180 top
U2 "LM3409MY/NOPB" MUC10A_N 2012.35,746.54 r0 top locked
U4 "UCC27511DBVR" DBV0006A_N 2506.93,1556.17 r180 top
U5 "LM3409MY/NOPB" MUC10A_N 2012.35,1871.54 r0 top locked
U7 "LP5907SNX-3.3/NOPB" DQN0004A 1122.5,3505 r180 top
U8 "LMR16006XDDCR" DDC0006A_N 431.5,3924 r270 top
U9 "LM5165DRCR" DRC0010J 1211,4158 r0 top
U10 "UCC27511DBVR" DBV0006A_N 2506.93,2681.17 r180 top
U11 "LM3409MY/NOPB" MUC10A_N 2012.35,2996.54 r0 top locked
U13 "UCC27511DBVR" DBV0006A_N 2506.93,3806.17 r180 top
U14 "LM3409MY/NOPB" MUC10A_N 2012.35,4121.54 r0 top locked
U17 "DAC7564ICPWR" PW0016A_N 793.31,2710.15 r180 top locked
VFB1 "5015" Testpoint_Keystone_Miniature 3331,824 r90 top
VFB2 "5015" Testpoint_Keystone_Miniature 3332,1949 r270 top
VFB3 "5015" Testpoint_Keystone_Miniature 3331,3074 r90 top
VFB4 "5015" Testpoint_Keystone_Miniature 3332,4199 r270 top
VIN+ "5015" Testpoint_Keystone_Miniature 870,4497 r90 top
VIN- "5015" Testpoint_Keystone_Miniature 350,4230.66 r180 top
WLED+ "5015" Testpoint_Keystone_Miniature 3378,4034 r180 top
WLED- "5015" Testpoint_Keystone_Miniature 3378,3896 r180 top
ZZ1 "This Assembly Note is for PCB labels only" AssemblyNoteLabel 260,5239 r0 top
ZZ2 "These assemblies are ESD sensitive, ESD precautions shall be observed." AssemblyNote 260,5110 r0 top
ZZ3 "These assemblies must be clean and free from flux and all contaminants. Use of no clean flux is not acceptable." AssemblyNote 260,4976 r0 top
ZZ4 "These assemblies must comply with workmanship standards IPC-A-610 Class 2, unless otherwise specified." AssemblyNote 268,4842 r0 top

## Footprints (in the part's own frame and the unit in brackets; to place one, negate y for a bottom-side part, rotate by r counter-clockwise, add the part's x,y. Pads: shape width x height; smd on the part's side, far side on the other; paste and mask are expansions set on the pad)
0201_033 [mm] "SMD, 2-Leads, Height 0.33mm"
  rect 0.46x0.42 smd mask+0.048: 1(-0.33,0) 2(0.33,0)
  body extent -0.31,-0.16 0.31,0.16, height 0.33
0402 [mm] "0402 from SM-752 data"
  rect 0.8x0.6 smd: 1(-0.6,0) 2(0.6,0)
  silkscreen extent -1.22,-0.52 1.22,0.52, body extent -0.55,-0.3 0.55,0.3, height 0.6
0603 [mm] "0603 from SM-752 data"
  rect 1x0.95 smd: 1(-0.8,0) 2(0.8,0)
  silkscreen extent -1.52,-0.69 1.52,0.69, body extent -0.87,-0.47 0.87,0.47, height 1
0805_HV [mil] "0805 with 30mil clearance between pads"
  rect 50x63 smd: 1(-40,0) 2(40,0)
  silkscreen extent -74,-40 74,40, body extent -43,-29 43,29, height 57
1206 [mm] "1206 from SM-752 data"
  rect 1.3x1.85 smd: 1(-1.45,0) 2(1.45,0)
  silkscreen extent -2.4,-1.21 2.4,1.21, body extent -1.7,-0.9 1.7,0.9, height 1.35
1206_180 [mm] "1206_180"
  rect 1.1x1.6 smd: 1(-1.7,0) 2(1.7,0)
  silkscreen extent -0.9,-1 0.9,1, body extent -1.75,-0.95 1.75,0.95, height 1.8
2512 [mm] "Chip Resistor, Body 6.3x3.2mm, IPC Medium Density"
  rect 1.3x3.4 smd: 1(-2.95,0) 2(2.95,0)
  silkscreen extent -1.9,-1.6 1.9,1.6, body extent -3.22,-1.67 3.22,1.67, height 0.71
AssemblyNote [mil] "Assembly Note"
AssemblyNoteLabel [mil] "Assembly Note for PCB Labels"
CONN_1751248 [mil] "Phoenix Contact"
  round 70 hole 43.31: 1(-68.9,0) 2(68.9,0)
  silkscreen extent -148,-142 148,146, body extent -148,-142 148,146, height 335
DBV0006A_N [mm] "SOT23, 6-Leads, Body 2.9x1.6mm, Pitch 0.95mm, Lead Span 2.8mm, IPC Medium Density"
  rrect17% 1x0.6 smd: 1(-1.375,0.95) 2(-1.375,0) 3(-1.375,-0.95) 4(1.375,-0.95) 5(1.375,0) 6(1.375,0.95)
  silkscreen extent -1.68,-1.55 0.5,1.55, body extent -1.42,-1.46 1.42,1.46, height 1.12
DDC0006A_N [mm]
  rrect17% 1x0.6 smd: 1(-1.375,0.95) 2(-1.375,0) 3(-1.375,-0.95) 4(1.375,-0.95) 5(1.375,0) 6(1.375,0.95)
  silkscreen extent -1.75,-1.52 0.7,1.53, body extent -1.43,-1.48 1.43,1.49, height 0.92
DPAK [mm] "D-PAK, 3-Pads, Body 6.22x6.73mm (max), TO-252AA using nominal STEP model"
  rrect6% 2.6x1.6 smd: 1(-3.4,2.28) 3(-3.4,-2.28)
  rrect2% 6.2x5.8 smd paste-2.9: 4(3.4,0)
  silkscreen extent -4.5,-3.3 4.7,3.28, body extent -3.86,-3.29 5.84,3.29, height 2.48
DQK0006C [mm] "WSON"
  rrect12% 0.9x0.86 on Bottom Paste: 0(0,0.325)
  rrect34% 0.7x0.29 on Bottom Paste: 0(0.095,-0.65)
  rrect33% 0.45x0.3 smd: 1(-0.975,0.65) 2(-0.975,0) 3(-0.975,-0.65) 4(0.975,-0.65) 5(0.975,0) 6(0.975,0.65)
  rrect33% 0.75x0.3 smd paste-0.15: 7(0.095,-0.65)
  rrect11% 1x0.95 smd paste-0.5: 8(0,0.325)
  silkscreen extent -1.15,-1.15 1.15,1.15, body extent -1,-1 1,1, height 0.82
DQN0004A [mm] "SON, 0.65mm pitch"
  rect 0.25x0.31 smd paste-1 mask-0.31: 1(-0.535,0.325) 2(-0.535,-0.325) 3(0.535,-0.325) 4(0.535,0.325)
  rect 0.58x0.58 smd rot 45 paste-0.065 mask-0.05: 5(0,0)
  Top Layer region: -0.66,0.48 -0.2,0.48 -0.2,0.379 -0.409,0.17 -0.66,0.17
  Top Layer region: 0.66,0.48 0.2,0.48 0.2,0.379 0.409,0.17 0.66,0.17
  Top Layer region: 0.66,-0.48 0.2,-0.48 0.2,-0.379 0.409,-0.17 0.66,-0.17
  Top Layer region: -0.66,-0.48 -0.2,-0.48 -0.2,-0.379 -0.409,-0.17 -0.66,-0.17
  silkscreen extent -0.88,-0.7 0.88,0.7, body extent -0.53,-0.53 0.53,0.53, height 0.42
DRC0010J [mm] "SON, 10-Leads, Body 3x3mm, Pitch 0.5mm, Thermal Pad 2.4x1.65mm, TI Recommended"
  rrect100% 0.6x0.24 smd: 1(-1.4,1) 2(-1.4,0.5) 3(-1.4,0) 4(-1.4,-0.5) 5(-1.4,-1) 6(1.4,-1) 7(1.4,-0.5) 8(1.4,0) 9(1.4,0.5) 10(1.4,1)
  rrect6% 1.65x2.4 smd paste-0.825: 11(0,0)
  silkscreen extent -1.7,-1.7 1.7,1.7, body extent -1.5,-1.5 1.5,1.5, height 0.77
Fiducial10-20 [mm]
  round 1 smd mask+0.5: 1(0,0)
  Top Layer keep-out circle w1.178: c0,0 r0.5
Keystone_1902C [mil] "Hex Standoff, 4-40 threaded, nylon"
  body extent -145,-126 146,126, height 501
Label_650x200 [mil] "Thermal Transfer Label"
  silkscreen extent -325,-100 325,100, body extent -325,-100 325,100, height 1
Mill-Max_800-10-002-10-001000 [mm] "Mill-Max"
  rect 1.5x1.5 hole 0.85: 1(-1.27,0)
  round 1.5 hole 0.85: 2(1.27,0)
  silkscreen extent -2.54,-1.27 2.54,1.78, body extent -2.54,-1.27 2.54,1.27, height 8.13
Molex_0022284033 [mm] "Header, 2.54mm, 3x1, TH"
  rect 1.55x1.55 hole 1.02: 1(-2.54,0)
  round 1.55 hole 1.02: 2(0,0) 3(2.54,0)
  silkscreen extent -3.81,-1.24 3.81,1.5, body extent -3.81,-1.24 3.81,1.24, height 8.4
MUC10A_N [mm] "TSSOP, 10-Leads, Body 3x3mm, Pitch 0.5mm, Exposed Pad, IPC Medium Density"
  rrect100% 1.35x0.3 smd: 1(-2.225,1) 2(-2.225,0.5) 3(-2.225,0) 4(-2.225,-0.5) 5(-2.225,-1) 6(2.225,-1) 7(2.225,-0.5) 8(2.225,0) 9(2.225,0.5) 10(2.225,1)
  rrect6% 1.73x1.9 smd: 11(0,0)
  silkscreen extent -2.73,-1.55 0.9,1.55, body extent -2.45,-1.5 2.45,1.5, height 0.96
"NY PMS 440 0025 PH" [mm] "4-40 nylon screw and mounting hole"
  round 8 hole 3.2: 1(0,0)
  body extent -3.3,-3.3 3.3,3.3, height 2.69
Pb-Free_Overlay_Small [mil]
  silkscreen extent -46,-46 46,46
PhoenixConact_1727010 [mm]
  rect 1.7x1.7 hole 1.1: 1(-1.905,0)
  round 1.7 hole 1.1: 2(1.905,0)
  silkscreen extent -4.8,-3.6 3.81,3.6, body extent -3.81,-3.6 3.81,3.7, height 8.52
PW0016A_N [mm] "TSOP, 16-Leads, Body 5x4.4mm, Pitch 0.65mm, IPC Medium Density"
  oval 1.4x0.45 smd: 1(-2.95,2.275) 2(-2.95,1.625) 3(-2.95,0.975) 4(-2.95,0.325) 5(-2.95,-0.325) 6(-2.95,-0.975) 7(-2.95,-1.625) 8(-2.95,-2.275) 9(2.95,-2.275) 10(2.95,-1.625) 11(2.95,-0.975) 12(2.95,-0.325) 13(2.95,0.325) 14(2.95,0.975) 15(2.95,1.625) 16(2.95,2.275)
  silkscreen extent -3.5,-2.55 1.85,2.75, body extent -3.21,-2.5 3.21,2.5, height 1
SDR0403 [mm] "BOURNS"
  rect 1.8x4.5 smd: 1(-1.65,0) 2(1.65,0)
  body extent -2.4,-2.4 2.4,2.4, height 3.3
SMC [mil] "Molded Diode, 2-Leads, Body 6.9x5.8mm, IPC Medium Density, based on OnSemi component dimensions and land patterns"
  rect 110x150 smd: 1(-140.49,0) 2(140.49,0)
  silkscreen extent -221,-123 189,124, body extent -156,-116 156,116, height 91
SOD-123FL [mm] "Copied from SOD-123"
  rect 0.915x1.22 smd: 1(-1.637,0) 2(1.637,0)
  silkscreen extent -2.74,-1.15 1.68,1.16, body extent -1.9,-0.9 1.9,0.9, height 1
SOD-323 [mm] "NXP recommended land pattern"
  rect 0.6x0.6 smd paste-0.05: 1(-1.1,0) 2(1.1,0)
  silkscreen extent -2.06,-0.86 1.53,0.86, body extent -1.3,-0.67 1.3,0.68, height 1.1
SULLINS_PEC10DAAN [mm] "SULLINS"
  rect 1.65x1.65 hole 1.016: 1(-1.27,11.43)
  round 1.65 hole 1.016: 2(1.27,11.43) 3(-1.27,8.89) 4(1.27,8.89) 5(-1.27,6.35) 6(1.27,6.35) 7(-1.27,3.81) 8(1.27,3.81) 9(-1.27,1.27) 10(1.27,1.27) 11(-1.27,-1.27) 12(1.27,-1.27) 13(-1.27,-3.81) 14(1.27,-3.81) 15(-1.27,-6.35) 16(1.27,-6.35) 17(-1.27,-8.89) 18(1.27,-8.89) 19(-1.27,-11.43) 20(1.27,-11.43)
  silkscreen extent -3.11,-12.96 2.79,13.25, body extent -2.79,-12.96 2.79,12.96, height 9.08
Testpoint_Keystone_Miniature [mil] "Miniature SMT test point"
  rect 135x70 smd: 1(0,0)
  silkscreen extent -78,-46 78,45, body extent -52,-20 52,20, height 61
"WE-PD_1245_METAL BASE" [mm] "SMD Inductor, 2-Leads, Body 12,0x12,0mm"
  rect 5.4x2.9 smd: 1(0,4.95) 2(0,-4.95)
  silkscreen extent -6,-6 6,6, body extent -6,-6 6,6, height 4.52
WE-TPC-LH [mm] "Wurth Elektronik recommended land pattern, 2009-01-15"
  rect 0.5x0.5 smd: 1(-2.7,0) 2(2.7,0)
  Top Layer region: 0.95,3.15 0.95,3.15 0.95,1.987 1.228,1.838 1.563,1.563 1.838,1.228 2.042,0.846 2.168,0.431 2.211,0 2.168,-0.431 2.042,-0.846 1.838,-1.228 1.563,-1.563 1.228,-1.838 0.95,-1.987 0.95,-3.15 3.15,-3.15 3.15,-3.15 3.15,3.15 0.95,3.15
  Top Layer region: -0.95,3.15 -0.95,3.15 -0.95,1.987 -1.228,1.838 -1.563,1.563 -1.838,1.228 -2.042,0.846 -2.168,0.431 -2.211,0 -2.168,-0.431 -2.042,-0.846 -1.838,-1.228 -1.563,-1.563 -1.228,-1.838 -0.95,-1.987 -0.95,-3.15 -3.15,-3.15 -3.15,-3.15 -3.15,3.15 -0.95,3.15
  silkscreen extent -3.4,-3.4 3.4,3.4, body extent -3.05,-3.05 3.05,3.05, height 3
